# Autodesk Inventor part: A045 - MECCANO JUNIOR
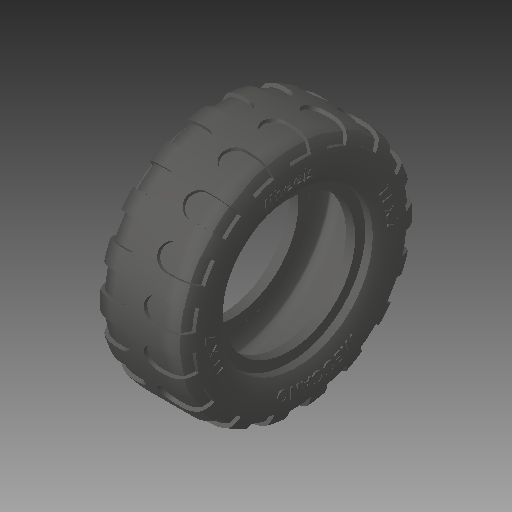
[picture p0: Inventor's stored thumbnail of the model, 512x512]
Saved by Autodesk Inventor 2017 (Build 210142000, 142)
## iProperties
Created: 2016-10
Part Number: A045 - MECCANO JUNIOR
Material: solidworks materials|PVC rigide
Document SubType Name: Modeling
Designer: ficho
Density: 1.3 g/cm^3
Appearance: 64,64,64
Mass: 24.1901 g
Surface Area: 231.214 cm^2
Volume: 18.6078 cm^3
Sending System: SolidWorks 2013
Last Author: lucie-nico
Last Saved: 2016-10-25
Author: ficho
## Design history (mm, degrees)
feature "Boss.-Extru.2"
node "Solide1"
